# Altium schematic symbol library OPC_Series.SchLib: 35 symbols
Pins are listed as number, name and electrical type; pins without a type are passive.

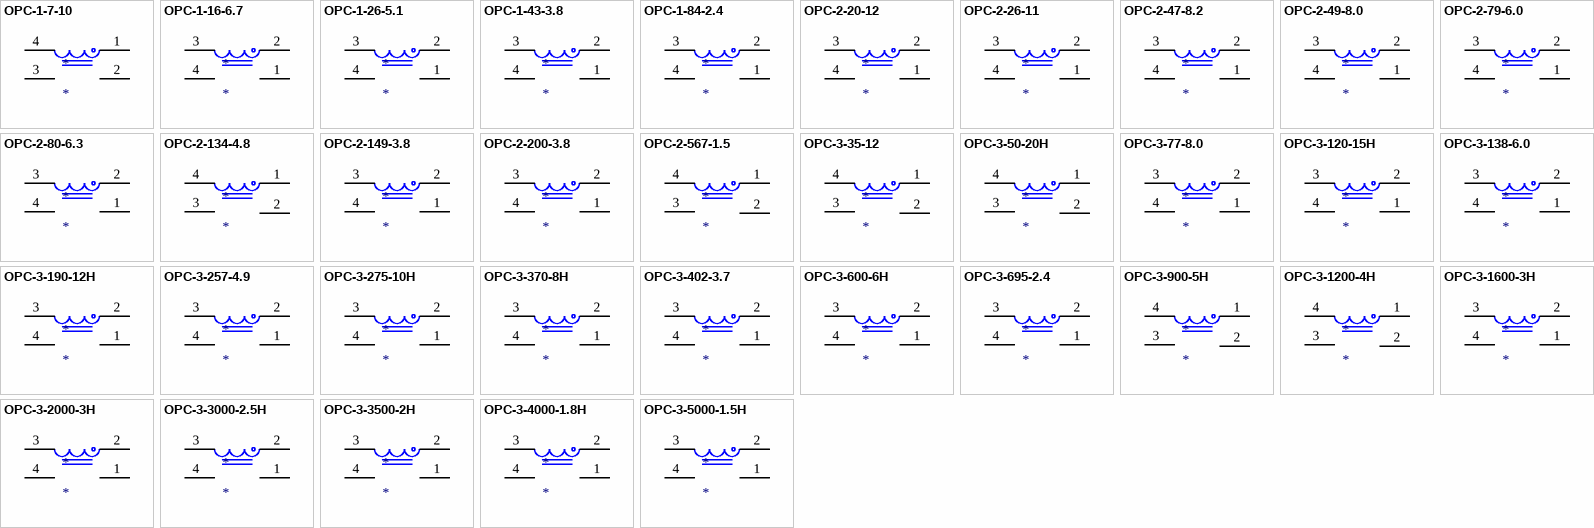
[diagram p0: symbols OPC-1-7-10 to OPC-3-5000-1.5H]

## OPC-1-7-10
designator *
POWER INDUCTOR 5 A, 2.2 mH, 630 mOhms, OD 29.46 mm, HT 21.08 mm; Manufacturer #1: CWS; Current: 10 A; DCR: 5.5 mOhms; LxWxH: 31.5 x 33.0 x 17.8 mm; Inductance: 7 uH; Description: POWER INDUCTOR 10 A, 7 uH, 5.5 mOhms, L x W x H  31.5 x 33.0 x 17.8 mm
footprint OPC-1-7-10
pins: 1, 2, 3, 4

## OPC-1-16-6.7
designator *
POWER INDUCTOR 5 A, 2.2 mH, 630 mOhms, OD 29.46 mm, HT 21.08 mm; Manufacturer #1: CWS; Current: 6.7 A; DCR: 7.7 mOhms; LxWxH: 31.5 x 33.0 x 17.8 mm; Inductance: 16 uH; Description: POWER INDUCTOR 6.7 A, 16 uH, 7.7 mOhms, L x W x H  31.5 x 33.0 x 17.8 mm
footprint OPC-1-16-6.7
pins: 1, 2, 3, 4

## OPC-1-26-5.1
designator *
POWER INDUCTOR 5 A, 2.2 mH, 630 mOhms, OD 29.46 mm, HT 21.08 mm; Manufacturer #1: CWS; Current: 5.1 A; DCR: 9.9 mOhms; LxWxH: 31.5 x 33.0 x 17.8 mm; Inductance: 26 uH; Description: POWER INDUCTOR 5.1 A, 26 uH, 9.9 mOhms, L x W x H  31.5 x 33.0 x 17.8 mm
footprint OPC-1-26-5.1
pins: 1, 2, 3, 4

## OPC-1-43-3.8
designator *
POWER INDUCTOR 5 A, 2.2 mH, 630 mOhms, OD 29.46 mm, HT 21.08 mm; Manufacturer #1: CWS; Current: 3.8 A; DCR: 12.1 mOhms; LxWxH: 31.5 x 33.0 x 17.8 mm; Inductance: 43 uH; Description: POWER INDUCTOR 3.8 A, 43 uH, 12.1 mOhms, L x W x H  31.5 x 33.0 x 17.8 mm
footprint OPC-1-43-3.8
pins: 1, 2, 3, 4

## OPC-1-84-2.4
designator *
POWER INDUCTOR 5 A, 2.2 mH, 630 mOhms, OD 29.46 mm, HT 21.08 mm; Manufacturer #1: CWS; Current: 2.4 A; DCR: 34.1 mOhms; LxWxH: 31.5 x 33.0 x 17.8 mm; Inductance: 84 uH; Description: POWER INDUCTOR 2.4 A, 84 uH, 34.1 mOhms, L x W x H  31.5 x 33.0 x 17.8 mm
footprint OPC-1-84-2.4
pins: 1, 2, 3, 4

## OPC-2-20-12
designator *
POWER INDUCTOR 5 A, 2.2 mH, 630 mOhms, OD 29.46 mm, HT 21.08 mm; Manufacturer #1: CWS; Current: 12 A; DCR: 8.8 mOhms; LxWxH: 43.2 x 40.6 x 22.9 mm; Inductance: 20 uH; Description: POWER INDUCTOR 12 A, 20 uH, 8.8 mOhms, L x W x H  43.2 x 40.6 x 22.9 mm
footprint OPC-2-20-12
pins: 1, 2, 3, 4

## OPC-2-26-11
designator *
POWER INDUCTOR 5 A, 2.2 mH, 630 mOhms, OD 29.46 mm, HT 21.08 mm; Manufacturer #1: CWS; Current: 11 A; DCR: 9.9 mOhms; LxWxH: 35.6 x 35.6 x 22.9 mm; Inductance: 26 uH; Description: POWER INDUCTOR 11 A, 26 uH, 9.9 mOhms, L x W x H  35.6 x 35.6 x 22.9 mm
footprint OPC-2-26-11
pins: 1, 2, 3, 4

## OPC-2-47-8.2
designator *
POWER INDUCTOR 5 A, 2.2 mH, 630 mOhms, OD 29.46 mm, HT 21.08 mm; Manufacturer #1: CWS; Current: 8.2 A; DCR: 13.2 mOhms; LxWxH: 35.6 x 35.6 x 22.9 mm; Inductance: 47 uH; Description: POWER INDUCTOR 8.2 A, 47 uH, 13.2 mOhms, L x W x H  35.6 x 35.6 x 22.9 mm
footprint OPC-2-47-8.2
pins: 1, 2, 3, 4

## OPC-2-49-8.0
designator *
POWER INDUCTOR 5 A, 2.2 mH, 630 mOhms, OD 29.46 mm, HT 21.08 mm; Manufacturer #1: CWS; Current: 8 A; DCR: 13.2 mOhms; LxWxH: 40.6 x 40.6 x 22.9 mm; Inductance: 49 uH; Description: POWER INDUCTOR 8 A, 49 uH, 13.2 mOhms, L x W x H  40.6 x 40.6 x 22.9 mm
footprint OPC-2-49-8.0
pins: 1, 2, 3, 4

## OPC-2-79-6.0
designator *
POWER INDUCTOR 5 A, 2.2 mH, 630 mOhms, OD 29.46 mm, HT 21.08 mm; Manufacturer #1: CWS; Current: 6 A; DCR: 16.5 mOhms; LxWxH: 35.6 x 35.6 x 22.9 mm; Inductance: 79 uH; Description: POWER INDUCTOR 6 A, 79 uH, 16.5 mOhms, L x W x H  35.6 x 35.6 x 22.9 mm
footprint OPC-2-79-6.0
pins: 1, 2, 3, 4

## OPC-2-80-6.3
designator *
POWER INDUCTOR 5 A, 2.2 mH, 630 mOhms, OD 29.46 mm, HT 21.08 mm; Manufacturer #1: CWS; Current: 6.3 A; DCR: 16.5 mOhms; LxWxH: 44.5 x 43.2 x 22.9 mm; Inductance: 80 uH; Description: POWER INDUCTOR 6.3 A, 80 uH, 16.5 mOhms, L x W x H  44.5 x 43.2 x 22.9 mm
footprint OPC-2-80-6.3
pins: 1, 2, 3, 4

## OPC-2-134-4.8
designator *
POWER INDUCTOR 5 A, 2.2 mH, 630 mOhms, OD 29.46 mm, HT 21.08 mm; Manufacturer #1: CWS; Current: 4.8 A; DCR: 22 mOhms; LxWxH: 40.6 x 40.6 x 22.9 mm; Inductance: 134 uH; Description: POWER INDUCTOR 4.8 A, 134 uH, 22 mOhms, L x W x H  40.6 x 40.6 x 22.9 mm
footprint OPC-2-134-4.8
pins: 1, 2, 3, 4

## OPC-2-149-3.8
designator *
POWER INDUCTOR 5 A, 2.2 mH, 630 mOhms, OD 29.46 mm, HT 21.08 mm; Manufacturer #1: CWS; Current: 3.8 A; DCR: 36.3 mOhms; LxWxH: 35.6 x 35.6 x 22.9 mm; Inductance: 149 uH; Description: POWER INDUCTOR 3.8 A, 149 uH, 36.3 mOhms, L x W x H  35.6 x 35.6 x 22.9 mm
footprint OPC-2-149-3.8
pins: 1, 2, 3, 4

## OPC-2-200-3.8
designator *
POWER INDUCTOR 5 A, 2.2 mH, 630 mOhms, OD 29.46 mm, HT 21.08 mm; Manufacturer #1: CWS; Current: 3.8 A; DCR: 41.8 mOhms; LxWxH: 40.6 x 40.6 x 22.9 mm; Inductance: 200 uH; Description: POWER INDUCTOR 3.8 A, 200 uH, 41.8 mOhms, L x W x H  40.6 x 40.6 x 22.9 mm
footprint OPC-2-200-3.8
pins: 1, 2, 3, 4

## OPC-2-567-1.5
designator *
POWER INDUCTOR 5 A, 2.2 mH, 630 mOhms, OD 29.46 mm, HT 21.08 mm; Manufacturer #1: CWS; Current: 1.5 A; DCR: 124.3 mOhms; LxWxH: 45.7 x 35.6 x 22.9 mm; Inductance: 567 uH; Description: POWER INDUCTOR 1.5 A, 567 uH, 124.3 mOhms, L x W x H  45.7 x 35.6 x 22.9 mm
footprint OPC-2-567-1.5
pins: 1, 2, 3, 4

## OPC-3-35-12
designator *
POWER INDUCTOR 5 A, 2.2 mH, 630 mOhms, OD 29.46 mm, HT 21.08 mm; Manufacturer #1: CWS; Current: 12 A; DCR: 8.8 mOhms; LxWxH: 40 x 35.56 x 23.86 mm; Inductance: 35 uH; Description: POWER INDUCTOR 12 A, 35 uH, 8.8 mOhms, L x W x H  40 x 35.56 x 23.86 mm
footprint OPC-3-35-12
pins: 1, 2, 3, 4

## OPC-3-50-20H
designator *
POWER INDUCTOR 5 A, 2.2 mH, 630 mOhms, OD 29.46 mm, HT 21.08 mm; Manufacturer #1: CWS; Current: 20 A; DCR: 6 mOhms; LxWxH: 45.72 x 35.56 x 22.86 mm; Inductance: 50 uH; Description: POWER INDUCTOR 20 A, 50 uH, 6 mOhms, L x W x H  45.72 x 35.56 x 22.86 mm
footprint OPC-3-50-20H
pins: 1, 2, 3, 4

## OPC-3-77-8.0
designator *
POWER INDUCTOR 5 A, 2.2 mH, 630 mOhms, OD 29.46 mm, HT 21.08 mm; Manufacturer #1: CWS; Current: 8 A; DCR: 13.2 mOhms; LxWxH: 40 x 35.56 x 23.86 mm; Inductance: 77 uH; Description: POWER INDUCTOR 8 A, 77 uH, 13.2 mOhms, L x W x H  40 x 35.56 x 23.86 mm
footprint OPC-3-77-8.0
pins: 1, 2, 3, 4

## OPC-3-120-15H
designator *
POWER INDUCTOR 5 A, 2.2 mH, 630 mOhms, OD 29.46 mm, HT 21.08 mm; Manufacturer #1: CWS; Current: 15 A; DCR: 14 mOhms; LxWxH: 45.72 x 35.56 x 22.86 mm; Inductance: 120 uH; Description: POWER INDUCTOR 15 A, 120 uH, 14 mOhms, L x W x H  45.72 x 35.56 x 22.86 mm
footprint OPC-3-120-15H
pins: 1, 2, 3, 4

## OPC-3-138-6.0
designator *
POWER INDUCTOR 5 A, 2.2 mH, 630 mOhms, OD 29.46 mm, HT 21.08 mm; Manufacturer #1: CWS; Current: 6 A; DCR: 27.5 mOhms; LxWxH: 45.72 x 35.56 x 22.86 mm; Inductance: 138 uH; Description: POWER INDUCTOR 6 A, 138 uH, 27.5 mOhms, L x W x H  45.72 x 35.56 x 22.86 mm
footprint OPC-3-138-6.0
pins: 1, 2, 3, 4

## OPC-3-190-12H
designator *
POWER INDUCTOR 5 A, 2.2 mH, 630 mOhms, OD 29.46 mm, HT 21.08 mm; Manufacturer #1: CWS; Current: 12 A; DCR: 17 mOhms; LxWxH: 45.72 x 35.56 x 22.86 mm; Inductance: 190 uH; Description: POWER INDUCTOR 12 A, 190 uH, 17 mOhms, L x W x H  45.72 x 35.56 x 22.86 mm
footprint OPC-3-190-12H
pins: 1, 2, 3, 4

## OPC-3-257-4.9
designator *
POWER INDUCTOR 5 A, 2.2 mH, 630 mOhms, OD 29.46 mm, HT 21.08 mm; Manufacturer #1: CWS; Current: 4.9 A; DCR: 37.4 mOhms; LxWxH: 40 x 35.56 x 23.86 mm; Inductance: 257 uH; Description: POWER INDUCTOR 4.9 A, 257 uH, 37.4 mOhms, L x W x H  40 x 35.56 x 23.86 mm
footprint OPC-3-257-4.9
pins: 1, 2, 3, 4

## OPC-3-275-10H
designator *
POWER INDUCTOR 5 A, 2.2 mH, 630 mOhms, OD 29.46 mm, HT 21.08 mm; Manufacturer #1: CWS; Current: 10 A; DCR: 26 mOhms; LxWxH: 40 x 35.56 x 23.86 mm; Inductance: 275 uH; Description: POWER INDUCTOR 10 A, 275 uH, 26 mOhms, L x W x H  40 x 35.56 x 23.86 mm
footprint OPC-3-275-10H
pins: 1, 2, 3, 4

## OPC-3-370-8H
designator *
POWER INDUCTOR 5 A, 2.2 mH, 630 mOhms, OD 29.46 mm, HT 21.08 mm; Manufacturer #1: CWS; Current: 8 A; DCR: 37 mOhms; LxWxH: 40 x 35.56 x 23.86 mm; Inductance: 370 uH; Description: POWER INDUCTOR 8 A, 370 uH, 37 mOhms, L x W x H  40 x 35.56 x 23.86 mm
footprint OPC-3-370-8H
pins: 1, 2, 3, 4

## OPC-3-402-3.7
designator *
POWER INDUCTOR 5 A, 2.2 mH, 630 mOhms, OD 29.46 mm, HT 21.08 mm; Manufacturer #1: CWS; Current: 3.7 A; DCR: 46.7 mOhms; LxWxH: 40 x 35.56 x 23.86 mm; Inductance: 402 uH; Description: POWER INDUCTOR 3.7 A, 402 uH, 46.7 mOhms, L x W x H  40 x 35.56 x 23.86 mm
footprint OPC-3-402-3.7
pins: 1, 2, 3, 4

## OPC-3-600-6H
designator *
POWER INDUCTOR 5 A, 2.2 mH, 630 mOhms, OD 29.46 mm, HT 21.08 mm; Manufacturer #1: CWS; Current: 6 A; DCR: 59 mOhms; LxWxH: 40 x 35.56 x 23.86 mm; Inductance: 600 uH; Description: POWER INDUCTOR 6 A, 600 uH, 59 mOhms, L x W x H  40 x 35.56 x 23.86 mm
footprint OPC-3-600-6H
pins: 1, 2, 3, 4

## OPC-3-695-2.4
designator *
POWER INDUCTOR 5 A, 2.2 mH, 630 mOhms, OD 29.46 mm, HT 21.08 mm; Manufacturer #1: CWS; Current: 2.4 A; DCR: 77 mOhms; LxWxH: 45.72 x 35.56 x 22.86 mm; Inductance: 695 uH; Description: POWER INDUCTOR 2.4 A, 695 uH, 77 mOhms, L x W x H  45.72 x 35.56 x 22.86 mm
footprint OPC-3-695-2.4
pins: 1, 2, 3, 4

## OPC-3-900-5H
designator *
POWER INDUCTOR 5 A, 2.2 mH, 630 mOhms, OD 29.46 mm, HT 21.08 mm; Manufacturer #1: CWS; Current: 5 A; DCR: 71 mOhms; LxWxH: 45.72 x 35.56 x 22.86 mm; Inductance: 900 uH; Description: POWER INDUCTOR 5 A, 900 uH, 71 mOhms, L x W x H  45.72 x 35.56 x 22.86 mm
footprint OPC-3-900-5H
pins: 1, 2, 3, 4

## OPC-3-1200-4H
designator *
POWER INDUCTOR 5 A, 2.2 mH, 630 mOhms, OD 29.46 mm, HT 21.08 mm; Manufacturer #1: CWS; Current: 4 A; DCR: 104 mOhms; LxWxH: 45.72 x 35.56 x 22.86 mm; Inductance: 1200 uH; Description: POWER INDUCTOR 4 A, 1200 uH, 104 mOhms, L x W x H  45.72 x 35.56 x 22.86 mm
footprint OPC-3-1200-4H
pins: 1, 2, 3, 4

## OPC-3-1600-3H
designator *
POWER INDUCTOR 5 A, 2.2 mH, 630 mOhms, OD 29.46 mm, HT 21.08 mm; Manufacturer #1: CWS; Current: 3 A; DCR: 150 mOhms; LxWxH: 45.72 x 35.56 x 22.86 mm; Inductance: 1600 uH; Description: POWER INDUCTOR 3 A, 1600 uH, 150 mOhms, L x W x H  45.72 x 35.56 x 22.86 mm
footprint OPC-3-1600-3H
pins: 1, 2, 3, 4

## OPC-3-2000-3H
designator *
POWER INDUCTOR 5 A, 2.2 mH, 630 mOhms, OD 29.46 mm, HT 21.08 mm; Manufacturer #1: CWS; Current: 3 A; DCR: 168 mOhms; LxWxH: 45.72 x 35.56 x 22.86 mm; Inductance: 2000 uH; Description: POWER INDUCTOR 3 A, 2000 uH, 168 mOhms, L x W x H  45.72 x 35.56 x 22.86 mm
footprint OPC-3-2000-3H
pins: 1, 2, 3, 4

## OPC-3-3000-2.5H
designator *
POWER INDUCTOR 5 A, 2.2 mH, 630 mOhms, OD 29.46 mm, HT 21.08 mm; Manufacturer #1: CWS; Current: 2.5 A; DCR: 260 mOhms; LxWxH: 45.72 x 35.56 x 22.86 mm; Inductance: 3000 uH; Description: POWER INDUCTOR 2.5 A, 3000 uH, 260 mOhms, L x W x H  45.72 x 35.56 x 22.86 mm
footprint OPC-3-3000-2.5H
pins: 1, 2, 3, 4

## OPC-3-3500-2H
designator *
POWER INDUCTOR 5 A, 2.2 mH, 630 mOhms, OD 29.46 mm, HT 21.08 mm; Manufacturer #1: CWS; Current: 2 A; DCR: 352 mOhms; LxWxH: 45.72 x 35.56 x 22.86 mm; Inductance: 3500 uH; Description: POWER INDUCTOR 2 A, 3500 uH, 352 mOhms, L x W x H  45.72 x 35.56 x 22.86 mm
footprint OPC-3-3500-2H
pins: 1, 2, 3, 4

## OPC-3-4000-1.8H
designator *
POWER INDUCTOR 5 A, 2.2 mH, 630 mOhms, OD 29.46 mm, HT 21.08 mm; Manufacturer #1: CWS; Current: 1.8 A; DCR: 376 mOhms; LxWxH: 40 x 35.56 x 23.86 mm; Inductance: 4 uH; Description: POWER INDUCTOR 1.8 A, 4 uH, 376 mOhms, L x W x H  40 x 35.56 x 23.86 mm
footprint OPC-3-4000-1.8H
pins: 1, 2, 3, 4

## OPC-3-5000-1.5H
designator *
POWER INDUCTOR 5 A, 2.2 mH, 630 mOhms, OD 29.46 mm, HT 21.08 mm; Manufacturer #1: CWS; Current: 1.5 A; DCR: 530 mOhms; LxWxH: 45.72 x 35.56 x 22.86 mm; Inductance: 5000 uH; Description: POWER INDUCTOR 1.5 A, 5000 uH, 530 mOhms, L x W x H  45.72 x 35.56 x 22.86 mm
footprint OPC-3-5000-1.5H
pins: 1, 2, 3, 4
